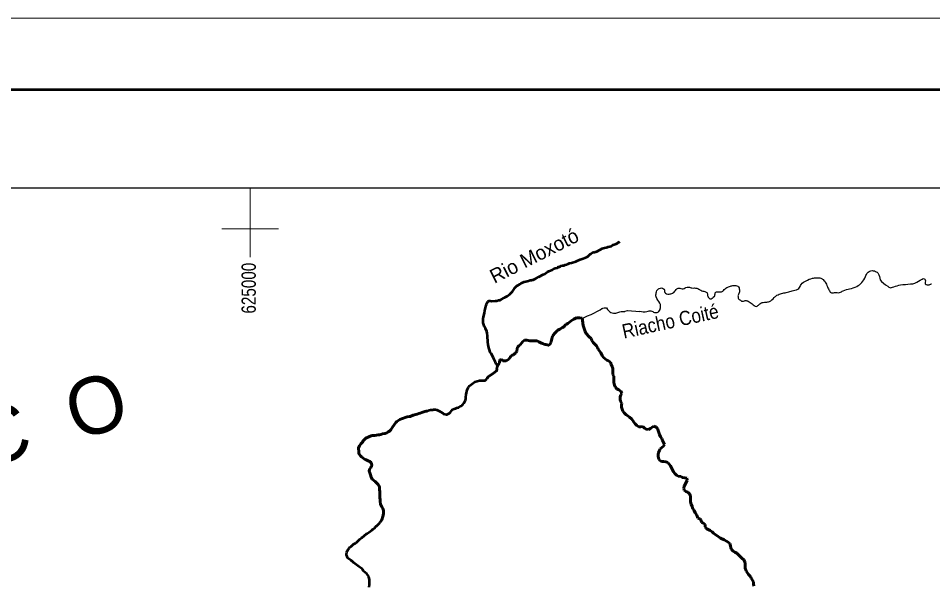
# Model space of a CAD drawing. Extents: x 553962 to 842807, y 8883888 to 9032388.
# Drawn here: x 616862 to 648955, y 9012512 to 9032388 of the extents above; entities that cross this region are included whole.
import ezdxf
from ezdxf.enums import TextEntityAlignment as Align

# ---------------------------------------------------------------- set-up
doc = ezdxf.new("R2010")
doc.units = 0
doc.header["$LTSCALE"] = 200
doc.linetypes.add('LONG_DASH_SHORT_DASH', pattern=[9.9, 6, -1.2, 1.5, -1.2])
for name, color, linetype, lineweight in [('2', 7, 'Continuous', 13), ('24', 7, 'Continuous', 25), ('3', 7, 'Continuous', 13), ('7', 7, 'LONG_DASH_SHORT_DASH', 60)]:
    doc.layers.add(name, color=color, linetype=linetype, lineweight=lineweight)
for name, color, linetype in [('42', 7, 'Continuous'), ('47', 7, 'Continuous'), ('49', 7, 'Continuous')]:
    doc.layers.add(name, color=color, linetype=linetype)

msp = doc.modelspace()

# ---------------------------------------------------------------- linework, layer by layer
at = {"layer": '2'}
for p, q in [((625000, 9024000), (625000, 9026438.8)), ((624000, 9025000), (626000, 9025000))]:
    msp.add_line(p, q, dxfattribs=at)
at = {"layer": '24', "lineweight": 53}
for points in [[(633413.9, 9022478.1), (633421.2, 9022477.1), (633480.4, 9022458.5), (633606.6, 9022474.9), (633658.1, 9022477.9), (633711.2, 9022491.3), (633762.6, 9022500.8), (633814.1, 9022520.8), (633917, 9022578.5), (633968.6, 9022613.4), (634020, 9022642.8), (634070.1, 9022674), (634114.4, 9022705.1), (634164.6, 9022749.5), (634211.6, 9022799.5), (634275.4, 9022905.1), (634276.2, 9022912.6), (634313.5, 9022956), (634360.5, 9022996.6), (634407, 9023028.7), (634463.3, 9023060.8), (634516.2, 9023093.9), (634619.2, 9023138.5), (634669.3, 9023151.8), (634720.7, 9023158.6), (634772.3, 9023177.5), (634823.9, 9023193.7), (634887.8, 9023203.3), (634902.5, 9023207.1), (634926.9, 9023210), (634978.4, 9023232.8), (635028.4, 9023251.7), (635132.8, 9023316), (635288.5, 9023394.6), (635338.7, 9023423), (635440.3, 9023486.3), (635485.1, 9023511.9), (635543.2, 9023541.2), (635595.9, 9023564.9), (635650.6, 9023598), (635699.1, 9023616), (635790.3, 9023636.1), (635793.1, 9023638), (635800.1, 9023649.3), (635819, 9023660.6), (635853.4, 9023668.3), (635876.7, 9023676.8), (635906.5, 9023697.6), (635956.5, 9023710), (636013.3, 9023718.7), (636059.5, 9023732.9), (636105.8, 9023750.9), (636162.5, 9023775.6), (636212.6, 9023793.6), (636275.1, 9023811.7), (636425, 9023859.2), (636478, 9023881.9), (636577.8, 9023919.9), (636690.9, 9023956), (636806.1, 9024008.1), (636823.2, 9024013.8), (636845.9, 9024034.6), (636912.2, 9024085.6), (636934.8, 9024108.2), (636956.3, 9024126.2), (637018.2, 9024171.5), (637057.1, 9024184.8), (637082.8, 9024185.8), (637104.5, 9024187.8), (637134.2, 9024195.4), (637161.3, 9024208.7), (637216.1, 9024229.5), (637230.8, 9024237.1), (637250.3, 9024253.2), (637273.6, 9024257.9), (637295.2, 9024272.1), (637314.4, 9024282.5), (637334, 9024298.6), (637359.5, 9024308.1), (637385.3, 9024320.4), (637537.2, 9024359.4), (637566.8, 9024363.3), (637618.3, 9024376.6), (637671, 9024396.6), (637718.9, 9024421.2), (637745.8, 9024437.2), (637770.3, 9024449.6), (637846.7, 9024469.6), (637851.3, 9024475.2), (637892.7, 9024501.7), (637913.2, 9024518.7), (637958, 9024544.2), (637971.9, 9024555.7)], [(633676.3, 9020181.4), (633676.3, 9020181.4), (633638.7, 9020264), (633612.2, 9020317.5), (633591.7, 9020369.2), (633563.5, 9020419.9), (633539.8, 9020471.5), (633453.9, 9020622.6), (633428.7, 9020672.4), (633401.8, 9020755.1), (633381.4, 9020829.3), (633365.3, 9020880), (633352.2, 9020933.6), (633345.6, 9021033.3), (633345, 9021086.9), (633332.3, 9021186.5), (633331.6, 9021241.1), (633318.4, 9021341.7), (633300.6, 9021397.1), (633254.7, 9021503.2), (633213.2, 9021588.7)], [(629274, 9017743.2), (629381.1, 9017748.3), (629434.5, 9017760.7), (629491.4, 9017765.6), (629537.5, 9017774.2), (629587.5, 9017786.6), (629642.2, 9017809.3), (629725.7, 9017821.8), (629743.8, 9017822.8), (629796.4, 9017840), (629846.5, 9017871.2), (629893.4, 9017902.3), (629935.3, 9017943.9), (629996.6, 9018037.2), (630048.9, 9018124.8), (630080.8, 9018160.6), (630113.1, 9018202.1), (630151.6, 9018240.8), (630254.2, 9018309.8), (630305.7, 9018332.6), (630507.3, 9018408.5), (630590.6, 9018415.3), (630611.9, 9018419.1), (630717.8, 9018458.1), (630816.3, 9018489.4), (630866, 9018499), (630920.7, 9018516.1), (630972.3, 9018535.1), (631025.1, 9018549.3), (631125.3, 9018586.4), (631186.5, 9018602.6), (631229.7, 9018616.8), (631281.3, 9018635.8), (631332.9, 9018645.4), (631418, 9018652.2), (631437.6, 9018655.1), (631504.9, 9018655.3), (631536.1, 9018652.6), (631547.1, 9018648.9), (631646.7, 9018604.1), (631758.6, 9018530.1), (631768.7, 9018519.8), (631780.5, 9018518), (631784.5, 9018507.7), (631788.3, 9018504.8), (631892.4, 9018481.7), (631899.2, 9018482.7), (631945.5, 9018503.5), (631993.7, 9018532.8), (632034.4, 9018569.6), (632106.5, 9018663.9), (632156.3, 9018682.9), (632209.2, 9018700), (632259.2, 9018719), (632312.1, 9018732.3), (632399.5, 9018775.8), (632439.6, 9018808.9), (632466.2, 9018835.3), (632501.5, 9018878.7), (632534.3, 9018936.2), (632553, 9018986.1), (632567.9, 9019034.1), (632569.1, 9019090.5), (632581.5, 9019191.2), (632619.5, 9019345.6), (632634.6, 9019396.4), (632664.3, 9019445.4), (632694.5, 9019486.9), (632744.2, 9019530.3), (632884.7, 9019635.2), (633050.2, 9019677.1), (633151.8, 9019677.4), (633222.6, 9019674.8), (633250.5, 9019683.4), (633294.8, 9019725.8), (633324, 9019767.3), (633357, 9019804.1), (633398.5, 9019840), (633496.1, 9019905.2), (633581.5, 9019968.5), (633647.8, 9020012.9), (633658.1, 9020043.1), (633663.7, 9020077.9), (633660.2, 9020090.1), (633676, 9020172.9), (633676.3, 9020181.4)], [(629194.7, 9016439.5), (629177.5, 9016494.9), (629187.5, 9016554.2), (629195.7, 9016563.6), (629200.5, 9016575.9), (629237.2, 9016624), (629245.2, 9016644.7), (629258.9, 9016658.8), (629261.5, 9016665.4), (629266.8, 9016705.9), (629260.6, 9016749.1), (629228.6, 9016818.6), (629200.8, 9016838.3), (629166.7, 9016852.3), (629065.4, 9016888.6), (629008.7, 9016922.3), (628959.7, 9016958.8), (628908.5, 9017002.8), (628868.8, 9017038.4), (628831.3, 9017088.2), (628817.9, 9017127.6), (628811.2, 9017173.7), (628801.7, 9017305.3), (628806.4, 9017311.9), (628840.5, 9017391), (628865.1, 9017422.1), (628888.6, 9017455.1), (628938, 9017517.3), (628963.8, 9017556), (628982.6, 9017573), (628987.4, 9017593.7), (629000, 9017599.4), (629064.4, 9017648.5), (629274, 9017743.2)], [(629251.8, 9016287.3), (629218.1, 9016364.3), (629194.7, 9016439.5)], [(628385.1, 9013563.7), (628384.6, 9013589.1), (628393.8, 9013653.1), (628406.8, 9013693.5), (628435.3, 9013742.5), (628473.3, 9013786.9), (628489.7, 9013813.2), (628501.5, 9013824.6), (628538.5, 9013852.9), (628556, 9013869.9), (628589.9, 9013894.5), (628628.8, 9013933.2), (628651.1, 9013946.4), (628673.7, 9013962.5), (628695.1, 9013973.8), (628729.5, 9013996.5), (628744.7, 9014007.8), (628779.8, 9014042.7), (628830.1, 9014083.3), (628852.5, 9014106), (628910.2, 9014151.3), (628933.9, 9014174), (629083.1, 9014298.6), (629109.7, 9014314.7), (629174, 9014361), (629226.4, 9014394.1), (629271.5, 9014426.2), (629294, 9014445.1), (629316.4, 9014466.8), (629374.3, 9014513.1), (629388, 9014530), (629412.2, 9014553.6), (629427.9, 9014564), (629444.5, 9014579.1), (629470.7, 9014596.1), (629485.8, 9014608.4), (629530.1, 9014656.5), (629544.5, 9014677.3), (629557.5, 9014702.7), (629568.8, 9014719.7), (629611.6, 9014775.3), (629622.1, 9014794.1), (629637.4, 9014828), (629647.2, 9014866.6), (629660.2, 9014906.2), (629668.7, 9014940.1), (629681.7, 9015019.1), (629682.1, 9015052), (629684.7, 9015087.8), (629681.2, 9015117.8), (629661.9, 9015180.8), (629623.3, 9015244.6), (629598, 9015294.4), (629587.7, 9015308.5), (629574.6, 9015342.3), (629564.7, 9015437.2), (629564.2, 9015501.2), (629551.4, 9015566), (629550.9, 9015690.2), (629547.7, 9015731.5), (629550.5, 9015763.5), (629550.4, 9015794.6), (629544.2, 9015827.5), (629543.7, 9015859.4), (629537.5, 9015892.3), (629533.8, 9015933.7), (629524.4, 9015973.2), (629518.3, 9015976.9), (629516.5, 9015989.1), (629490.5, 9016027.6), (629451.9, 9016059.4), (629382.5, 9016129.8), (629285.4, 9016211.2), (629251.8, 9016287.3)], [(629172, 9012423.6), (629184.2, 9012523.3), (629184.4, 9012576), (629190.2, 9012625.9), (629183.6, 9012680.4), (629167.1, 9012786.6), (629159.2, 9012796.9), (629128.4, 9012844.8), (629090.7, 9012887.9), (628980.3, 9012992.9), (628979, 9013000.4), (628970.9, 9013002.3), (628969.2, 9013017.3), (628950.2, 9013031.4), (628929.8, 9013068.9), (628829.8, 9013142.9), (628780.7, 9013176.6), (628727.8, 9013209.3), (628680.6, 9013243), (628636, 9013283.3), (628574.8, 9013335.8), (628552.3, 9013351.7), (628548.7, 9013360.1), (628427, 9013439.7), (628422.5, 9013448.1), (628385.1, 9013563.7)]]:
    msp.add_lwpolyline(points, dxfattribs=at)
at = {"layer": '24'}
for points in [[(636656.2, 9021865), (636684.9, 9021860.4), (636702.2, 9021873.6), (636740.9, 9021895.4), (636792.1, 9021921.9), (636838.7, 9021941.8), (636972.2, 9021990.2), (637015.9, 9022012), (637062.3, 9022041.3), (637193.3, 9022116), (637241.1, 9022134), (637284.8, 9022155.8), (637346, 9022200.2), (637368.3, 9022205), (637375.3, 9022213.5), (637379.5, 9022215.4), (637419.9, 9022224), (637504.2, 9022227.1), (637543.1, 9022171.7), (637575.9, 9022133.2), (637622.8, 9022093), (637661.8, 9022064.9), (637705.5, 9022049), (637750.8, 9022037), (637835.6, 9022037.2), (637934, 9022078.9), (637976.1, 9022088.5), (638019.7, 9022095.2), (638067.9, 9022095.4), (638139.8, 9022101.2), (638145.1, 9022104.1), (638157.6, 9022114.5), (638245.3, 9022132.2), (638672.6, 9022102.2)], [(636652.9, 9021868), (636641.6, 9021870.8), (636559.2, 9021880.9), (636454.2, 9021872.1), (636402.3, 9021849.3), (636354.6, 9021825.7), (636305.7, 9021795.4), (636263.9, 9021766.1), (636146.2, 9021677.3), (636105.2, 9021649), (636073, 9021625.4), (636004.2, 9021562.1), (635963.7, 9021536.6), (635867.3, 9021484.6), (635822.2, 9021456.2), (635780.5, 9021426.9), (635747.3, 9021396.7), (635692.5, 9021336.3), (635636.6, 9021264.7), (635616.1, 9021229.8), (635597.2, 9021191.2), (635584.4, 9021142.2), (635566, 9021043.4), (635559.6, 9021026.5), (635512, 9020943.6), (635480.4, 9020919), (635466.2, 9020917.1), (635380.8, 9020937.5), (635326.8, 9020945.8), (635298.1, 9020960.7), (635224.4, 9020989.6), (635174.2, 9021011.1), (635133.8, 9021040.1), (635075.6, 9021068.1), (634924.4, 9021068.6), (634868.1, 9021065.6), (634816.6, 9021072), (634714.8, 9021096.1), (634640.3, 9021095.8), (634633, 9021094.9), (634564.5, 9021042.9), (634472.5, 9020927.9), (634430.9, 9020895.8), (634394.5, 9020859), (634385.7, 9020847.7), (634383.8, 9020843), (634383.1, 9020829.8), (634371.1, 9020810.9), (634361.3, 9020698.1), (634352.5, 9020683), (634342.1, 9020680.1), (634329, 9020647.2), (634305.8, 9020635.8), (634240.7, 9020580.1), (634199.2, 9020572.4), (634144.7, 9020528.1), (634139.6, 9020509.2), (634131.3, 9020504.5), (634076.6, 9020431.9), (634046.6, 9020405.5), (633987.2, 9020367.7), (633978.5, 9020365.7), (633894.3, 9020363.6), (633891.4, 9020364.5), (633885.4, 9020372), (633871.8, 9020372.9), (633850.3, 9020386), (633845.5, 9020394.5), (633828.1, 9020398.2), (633817.3, 9020409.4), (633770.7, 9020403.6), (633766, 9020385.7), (633755.6, 9020376.3), (633753.8, 9020373.5), (633746.2, 9020297.3), (633676.3, 9020181.4)]]:
    msp.add_lwpolyline(points, dxfattribs=at)
for points in [[(646464.4, 9023111), (646597.9, 9023326), (646667.6, 9023459.6), (646783.8, 9023529.3), (646946.4, 9023506.1), (647045.1, 9023430.6), (647114.8, 9023215.6), (647376.1, 9022983.1), (647445.8, 9022936.6), (647585.1, 9022965.7), (647823.2, 9023029.6), (648171.7, 9023064.5), (648328.4, 9023093.5), (648589.8, 9023238.8), (648659.5, 9023250.4), (648694.3, 9023209.7), (648694.3, 9023064.5), (648758.2, 9023035.4), (648885.9, 9023058.7), (648910.6, 9023071.8)], [(638666.8, 9022105.1), (638926.3, 9022102.2), (638999.8, 9022122.2), (639130, 9022095.5), (639190.1, 9022065.4), (639313.6, 9022075.5), (639347, 9022095.5), (639387.1, 9022169), (639403.7, 9022285.9), (639377, 9022396.2), (639250.2, 9022610), (639250.2, 9022753.6), (639276.9, 9022830.4), (639360.3, 9022907.3), (639440.5, 9022924), (639537.3, 9022850.5), (639540.6, 9022797), (639654.1, 9022710.2), (639764.3, 9022720.2), (639877.8, 9022780.3), (639974.6, 9022897.2), (640074.8, 9022920.6), (640164.9, 9022893.9), (640295.1, 9022944), (640388.6, 9022957.4), (640502.1, 9022924), (640592.2, 9022924), (640749.2, 9022883.9), (640785.9, 9022860.5), (640815.9, 9022843.8), (640962.8, 9022797), (641029.6, 9022760.3), (641042.9, 9022740.2), (641059.6, 9022633.3), (641109.7, 9022563.2), (641136.4, 9022543.1), (641216.5, 9022566.5), (641253.3, 9022593.2), (641266.6, 9022610), (641293.3, 9022630), (641323.4, 9022750.3), (641363.4, 9022787), (641433.5, 9022793.7), (641493.6, 9022787), (641583.8, 9022813.7), (641697.3, 9022920.6), (641827.5, 9022977.4), (641937.7, 9023010.8), (642004.4, 9023010.8), (642084.6, 9022997.5), (642144.6, 9022967.4), (642168, 9022893.9), (642164.7, 9022750.3), (642121.3, 9022650), (642128, 9022589.9), (642134.6, 9022543.1), (642208.1, 9022493), (642248.1, 9022466.3), (642378.3, 9022483), (642481.8, 9022459.6), (642548.6, 9022416.2), (642685.5, 9022306), (642718.9, 9022282.6), (642795.7, 9022289.2), (642892.5, 9022369.4), (643002.6, 9022419.5), (643109.5, 9022426.2), (643223, 9022452.9), (643393.2, 9022586.6), (643486.7, 9022666.7), (643653.6, 9022733.6), (643810.5, 9022763.6), (643904, 9022783.7), (644067.6, 9022833.8), (644254.6, 9022910.6), (644338, 9023047.6), (644511.6, 9023177.9), (644735.3, 9023264.7), (644882.2, 9023284.8), (645025.8, 9023268.1), (645112.6, 9023218), (645202.7, 9023094.3), (645276.1, 9022927.3), (645349.6, 9022797), (645376.3, 9022760.3), (645506.5, 9022767), (645686.2, 9022762.3), (645814, 9022826.2), (646040.5, 9022896), (646290.2, 9022977.3), (646464.4, 9023111)]]:
    msp.add_spline(points, degree=3, dxfattribs=at)
at = {"layer": '24', "lineweight": 53}
msp.add_spline([(633213.2, 9021588.7), (633176.5, 9021739.5), (633198.3, 9021957.3), (633285, 9022315.7), (633329, 9022430.2), (633413.9, 9022478.1)], degree=3, dxfattribs=at)
at = {"layer": '3'}
msp.add_lwpolyline([(842807.3, 9032387.8), (842807.3, 8883887.8), (553961.7, 8883887.8), (553961.7, 9032387.8)], close=True, dxfattribs=at)
msp.add_lwpolyline([(842807.3, 9032387.8), (842807.3, 8883887.8), (553961.7, 8883887.8), (553961.7, 9032387.8)], close=True, dxfattribs=at)
at = {"layer": '3', "lineweight": 53}
msp.add_lwpolyline([(840307.3, 9029887.8), (840307.3, 8886387.8), (560211.7, 8886387.8), (560211.7, 9029887.8)], close=True, dxfattribs=at)
msp.add_lwpolyline([(840307.3, 9029887.8), (840307.3, 8886387.8), (560211.7, 8886387.8), (560211.7, 9029887.8)], close=True, dxfattribs=at)
at = {"layer": '3', "lineweight": 25}
msp.add_lwpolyline([(563033.9, 9026438.8), (793061.1, 9026438.8), (793495.6, 8889836.8), (563468.3, 8889836.8)], close=True, dxfattribs=at)
msp.add_lwpolyline([(563033.9, 9026438.8), (793061.1, 9026438.8), (793495.6, 8889836.8), (563468.3, 8889836.8)], close=True, dxfattribs=at)
at = {"layer": '7'}
for points in [[(636652.9, 9021868), (636641.6, 9021870.8), (636559.2, 9021880.9), (636454.2, 9021872.1), (636402.3, 9021849.3), (636354.6, 9021825.7), (636305.7, 9021795.4), (636263.9, 9021766.1), (636146.2, 9021677.3), (636105.2, 9021649), (636073, 9021625.4), (636004.2, 9021562.1), (635963.7, 9021536.6), (635867.3, 9021484.6), (635822.2, 9021456.2), (635780.5, 9021426.9), (635747.3, 9021396.7), (635692.5, 9021336.3), (635636.6, 9021264.7), (635616.1, 9021229.8), (635597.2, 9021191.2), (635584.4, 9021142.2), (635566, 9021043.4), (635559.6, 9021026.5), (635512, 9020943.6), (635480.4, 9020919), (635466.2, 9020917.1), (635380.8, 9020937.5), (635326.8, 9020945.8), (635298.1, 9020960.7), (635224.4, 9020989.6), (635174.2, 9021011.1), (635133.8, 9021040.1), (635075.6, 9021068.1), (634924.4, 9021068.6), (634868.1, 9021065.6), (634816.6, 9021072), (634714.8, 9021096.1), (634640.3, 9021095.8), (634633, 9021094.9), (634564.5, 9021042.9), (634472.5, 9020927.9), (634430.9, 9020895.8), (634394.5, 9020859), (634385.7, 9020847.7), (634383.8, 9020843), (634383.1, 9020829.8), (634371.1, 9020810.9), (634361.3, 9020698.1), (634352.5, 9020683), (634342.1, 9020680.1), (634329, 9020647.2), (634305.8, 9020635.8), (634240.7, 9020580.1), (634199.2, 9020572.4), (634144.7, 9020528.1), (634139.6, 9020509.2), (634131.3, 9020504.5), (634076.6, 9020431.9), (634046.6, 9020405.5), (633987.2, 9020367.7), (633978.5, 9020365.7), (633894.3, 9020363.6), (633891.4, 9020364.5), (633885.4, 9020372), (633871.8, 9020372.9), (633850.3, 9020386), (633845.5, 9020394.5), (633828.1, 9020398.2), (633817.3, 9020409.4), (633770.7, 9020403.6), (633766, 9020385.7), (633755.6, 9020376.3), (633753.8, 9020373.5), (633746.2, 9020297.3), (633676.3, 9020181.4)], [(638704.2, 9018056.3), (638636.4, 9018051), (638565.9, 9018103.4), (638512.9, 9018158.4), (638467.5, 9018221), (638429.6, 9018278.6), (638384.1, 9018333.6), (638318.6, 9018391.1), (638250.6, 9018436), (638195.2, 9018478.4), (638127.1, 9018538.4), (638081.6, 9018601), (638030.9, 9018738.8), (638035.6, 9018816.7), (638045.4, 9018887), (638002.5, 9018942.1), (637984.6, 9019017.3), (637986.8, 9019100.2), (638006.7, 9019173), (638041.6, 9019238.5), (638006.2, 9019308.6), (637935.7, 9019353.5), (637870.2, 9019383.3), (637807.2, 9019450.8), (637784.3, 9019518.5), (637768.9, 9019603.8), (637768.4, 9019759.5), (637765.6, 9019827.2), (637732.7, 9019892.4), (637732.2, 9020033), (637726.9, 9020100.7), (637706.6, 9020170.9), (637671.2, 9020236), (637648.2, 9020316.3), (637577.7, 9020368.7), (637514.8, 9020396), (637454.3, 9020436), (637403.9, 9020488.5), (637355.9, 9020556), (637307.9, 9020643.7), (637216.9, 9020773.9), (637189.1, 9020836.5), (637151.2, 9020894.1), (637100.7, 9020954.1), (637042.7, 9021016.6), (636994.7, 9021076.7), (636964.3, 9021146.8), (636898.8, 9021209.3), (636797.8, 9021321.9), (636752.3, 9021397), (636734.5, 9021467.2), (636684.8, 9021608.7), (636652.9, 9021875.9)], [(633316.8, 9019757.1), (633324, 9019767.3), (633357, 9019804.1), (633398.5, 9019840), (633496.1, 9019905.2), (633581.5, 9019968.5), (633647.8, 9020012.9), (633658.1, 9020043.1)], [(629274, 9017743.2), (629381.1, 9017748.3), (629434.5, 9017760.7), (629491.4, 9017765.6), (629537.5, 9017774.2), (629587.5, 9017786.6), (629642.2, 9017809.3), (629725.7, 9017821.8), (629743.8, 9017822.8), (629796.4, 9017840), (629846.5, 9017871.2), (629893.4, 9017902.3), (629935.3, 9017943.9), (629996.6, 9018037.2), (630048.9, 9018124.8), (630080.8, 9018160.6), (630113.1, 9018202.1), (630151.6, 9018240.8), (630254.2, 9018309.8), (630305.7, 9018332.6), (630507.3, 9018408.5), (630590.6, 9018415.3), (630611.9, 9018419.1), (630717.8, 9018458.1), (630816.3, 9018489.4), (630866, 9018499), (630920.7, 9018516.1), (630972.3, 9018535.1), (631025.1, 9018549.3), (631125.3, 9018586.4), (631186.5, 9018602.6), (631213.4, 9018611.4)], [(639653.5, 9016800.1), (639585.6, 9016819.9), (639510.2, 9016829.6), (639439.8, 9016831.8), (639379.4, 9016866.7), (639339, 9016921.8), (639318.6, 9017007.1), (639315.8, 9017084.9), (639335.7, 9017150.2), (639360.6, 9017215.6), (639393, 9017276), (639445.6, 9017326.4), (639505.7, 9017374.4), (639538.1, 9017437.3), (639502.7, 9017502.4), (639469.8, 9017575.1), (639444.4, 9017645.2), (639401.5, 9017705.3), (639368.5, 9017778), (639348.2, 9017850.7), (639317.8, 9017925.9), (639297.4, 9017996.1), (639247, 9018043.6), (639169, 9018075.9), (639103.8, 9018040.5), (639046.1, 9017997.5), (638980.9, 9017962.1), (638900.5, 9017964.3), (638835.1, 9018006.7), (638779.6, 9018059.2), (638704.2, 9018056.3)], [(629194.7, 9016439.5), (629177.5, 9016494.9), (629187.5, 9016554.2), (629195.7, 9016563.6), (629200.5, 9016575.9), (629237.2, 9016624), (629245.2, 9016644.7), (629258.9, 9016658.8), (629261.5, 9016665.4), (629266.8, 9016705.9), (629260.6, 9016749.1), (629228.6, 9016818.6), (629200.8, 9016838.3), (629166.7, 9016852.3), (629065.4, 9016888.6), (629008.7, 9016922.3), (628959.7, 9016958.8), (628908.5, 9017002.8), (628868.8, 9017038.4), (628831.3, 9017088.2), (628817.9, 9017127.6), (628811.2, 9017173.7), (628801.7, 9017305.3), (628806.4, 9017311.9), (628840.5, 9017391), (628865.1, 9017422.1), (628888.6, 9017455.1), (628938, 9017517.3), (628963.8, 9017556), (628982.6, 9017573), (628987.4, 9017593.7), (629000, 9017599.4), (629064.4, 9017648.5), (629274, 9017743.2)], [(642587.9, 9012738.2), (642555, 9012803.3), (642491.9, 9012875.8), (642449, 9012935.9), (642411, 9013003.5), (642378, 9013091.2), (642377.5, 9013241.9), (642359.6, 9013319.6), (642321.7, 9013387.2), (642261.2, 9013447.2), (642084.7, 9013614.7), (642014.2, 9013649.5), (641953.8, 9013686.9), (641888.2, 9013741.9), (641865.4, 9013807), (641855.1, 9013874.8), (641829.7, 9013952.5), (641771.7, 9014002.5), (641713.8, 9014044.9), (641640.8, 9014087.2), (641512.4, 9014146.9), (641383.9, 9014239.3), (641316, 9014271.6), (641260.5, 9014321.6), (641210.1, 9014371.6), (641144.6, 9014416.5), (641071.7, 9014443.8), (641003.7, 9014483.7), (640965.8, 9014543.8), (640965.5, 9014626.6), (640912.5, 9014674.1), (640844.6, 9014691.4), (640824.2, 9014771.6), (640776.3, 9014821.6), (640713.4, 9014849), (640683, 9014911.6), (640660.2, 9014976.8), (640614.7, 9015039.3), (640579.2, 9015117), (640541.3, 9015177.1), (640508.4, 9015254.8), (640472.9, 9015332.5), (640455.1, 9015415.2), (640454.5, 9015560.8), (640451.7, 9015636.1), (640416.3, 9015703.8), (640355.8, 9015758.8), (640287.9, 9015781.1), (640227.4, 9015828.5), (640219.6, 9015903.8), (640236.9, 9015971.6), (640304.3, 9016102.5), (640336.7, 9016177.9), (640326.4, 9016245.7), (640251, 9016257.9), (640175.5, 9016277.7), (640112.6, 9016305), (640024.6, 9016322.2), (639961.7, 9016357.1), (639898.7, 9016409.5), (639855.7, 9016474.6), (639827.8, 9016547.3), (639754.4, 9016687.6), (639704, 9016747.6), (639653.5, 9016800.1)], [(629251.8, 9016287.3), (629218.1, 9016364.3), (629194.7, 9016439.5)], [(629568.8, 9014719.7), (629611.6, 9014775.3), (629622.1, 9014794.1), (629637.4, 9014828), (629647.2, 9014866.6), (629660.2, 9014906.2), (629668.7, 9014940.1), (629681.7, 9015019.1), (629682.1, 9015052), (629684.7, 9015087.8), (629681.2, 9015117.8), (629661.9, 9015180.8), (629623.3, 9015244.6), (629598, 9015294.4), (629587.7, 9015308.5), (629574.6, 9015342.3), (629564.7, 9015437.2), (629564.2, 9015501.2), (629551.4, 9015566), (629550.9, 9015690.2), (629547.7, 9015731.5), (629550.5, 9015763.5), (629550.4, 9015794.6), (629544.2, 9015827.5), (629543.7, 9015859.4), (629537.5, 9015892.3), (629533.8, 9015933.7), (629524.4, 9015973.2), (629518.3, 9015976.9), (629516.5, 9015989.1), (629490.5, 9016027.6), (629451.9, 9016059.4), (629382.5, 9016129.8), (629285.4, 9016211.2), (629251.8, 9016287.3)], [(642674.3, 9012462.4), (642669, 9012537.7), (642668.7, 9012615.5), (642587.9, 9012738.2)]]:
    msp.add_lwpolyline(points, dxfattribs=at)

# ---------------------------------------------------------------- texts
at = {"layer": '42'}
msp.add_text('P  E  R  N  A  M  B  U  C  O', height=2000, rotation=16.855, dxfattribs=at).set_placement((589730.9, 9008723.5))
at = {"layer": '47', "width": 0.8}
msp.add_text('625000', height=500, rotation=90, dxfattribs=at).set_placement((625197.3, 9022917.4), align=Align.CENTER)
at = {"layer": '49'}
msp.add_text('Rio Moxotó', height=500, rotation=26.825, dxfattribs=at).set_placement((635080.7, 9023830.7), align=Align.CENTER)
at = {"layer": '49', "width": 0.9}
msp.add_text('Riacho Coité', height=500, rotation=12.335, dxfattribs=at).set_placement((639799.3, 9021513.7), align=Align.CENTER)

doc.saveas('drawing.dxf')
